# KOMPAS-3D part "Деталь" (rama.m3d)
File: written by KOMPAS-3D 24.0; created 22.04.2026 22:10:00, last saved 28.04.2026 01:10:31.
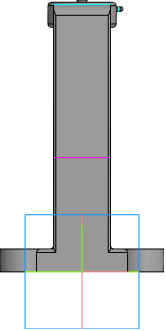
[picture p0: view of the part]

Document properties: Автор: mrdid; Полное имя файла: C:\Работа\ГОТОВЫЕ ИСХОДНИКИ\VSO2130M-F-S Клапан запорный сильфонный DN.ru Ду15-100 Ру40\исходные материалы\DN25\rama.m3d

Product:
- Part/product: Деталь
    Масса: 1.121141

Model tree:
1. Эскиз:2  (with: Ребро.Элемент выдавливания:14)
2. Элемент выдавливания:1
     Расстояние 1 = 10
3. Эскиз:3  (with: Грань.Элемент выдавливания:1, Ребро.Элемент выдавливания:1)
4. Элемент выдавливания:2
     Расстояние 2 = 10
5. Эскиз:4  (with: Грань.Элемент выдавливания:1)
6. Элемент выдавливания:3
     Расстояние 1 = 4.5
7. Эскиз:5  (with: Грань.Элемент выдавливания:3, Ребро.Элемент выдавливания:3)
8. Элемент выдавливания:4
     Расстояние 1 = 10
9. Эскиз:6  (with: Грань.Элемент выдавливания:1, Ребро.Элемент выдавливания:1)
10. Элемент выдавливания:5
     Расстояние 1 = 40
11. Эскиз:23  (with: Грань.Элемент выдавливания:4, Ребро.Элемент выдавливания:4)
12. Элемент выдавливания:21
     Расстояние 1 = 11
13. Эскиз:7  (with: Грань.Элемент выдавливания:21, Ребро.Элемент выдавливания:3)
14. Элемент выдавливания:6
     Расстояние 2 = 3
15. Эскиз:8  (with: Грань.Элемент выдавливания:5, Ребро.Элемент выдавливания:5)
16. Смещенная плоскость:1  (with: Грань.Элемент выдавливания:5)
17. Эскиз:9
18. Элемент по сечениям:1
19. Элемент по сечениям:2
20. Эскиз:10
21. Элемент выдавливания:8
     Расстояние 2 = 6
22. Эскиз:11  (with: Грань.Элемент выдавливания:8, Ребро.Элемент выдавливания:3)
23. Элемент выдавливания:9  (with: Грань.Элемент выдавливания:8)
     Расстояние 1 = 1; Расстояние 2 = 10; Смещение 2 = 4
24. Эскиз:12  (with: Грань.Элемент выдавливания:9, Ребро.Элемент выдавливания:9)
25. Элемент выдавливания:10
     Расстояние 1 = 5
26. Эскиз:13  (with: Грань.Элемент выдавливания:21, Ребро.Элемент выдавливания:3)
27. Элемент выдавливания:11  (with: Грань.Элемент выдавливания:10)
     Расстояние 1 = 66.488
28. Смещенная плоскость:2  (with: Грань.Элемент выдавливания:21)
29. Эскиз:14  (with: Ребро.Элемент по сечениям:2, Ребро.Элемент по сечениям:1)
30. Элемент выдавливания:12
     Расстояние 1 = 5
31. Эскиз:15  (with: Грань.Элемент выдавливания:12, Ребро.Элемент выдавливания:3)
32. Элемент выдавливания:13
     Расстояние 1 = 5
33. Эскиз:16  (with: Ребро.Элемент выдавливания:5, Ребро.Элемент выдавливания:1, Ребро.Элемент выдавливания:4)
34. Элемент выдавливания:14
     Расстояние 1 = 4
35. Элемент выдавливания:15
     Расстояние 1 = 2
36. Эскиз:17  (with: Ребро.Элемент выдавливания:5, Ребро.Элемент выдавливания:14)
37. Элемент выдавливания:16
     Расстояние 1 = 36
38. Скругление:1  (with: Ребро.Элемент выдавливания:1, Ребро.Элемент выдавливания:3)
     Радиус = 1.5
39. Скругление:2  (with: Ребро.Элемент выдавливания:9, Ребро.Элемент выдавливания:10, Ребро.Элемент выдавливания:13, Ребро.Элемент выдавливания:4)
40. Эскиз:18  (with: Грань.Элемент выдавливания:9)
41. Элемент выдавливания:17
     Расстояние 1 = 1
42. Скругление:3  (with: Ребро.Элемент по сечениям:2, Ребро.Элемент по сечениям:1)
     Радиус = 5
43. Скругление:4  (with: Ребро.Элемент выдавливания:8)
     Радиус = 0.5
44. Скругление:5  (with: Ребро.Элемент выдавливания:14)
     Радиус = 5
45. Эскиз:19  (with: Ребро.Элемент выдавливания:17)
46. Элемент выдавливания:18  (with: Грань.Элемент выдавливания:9)
     Смещение 1 = 5
47. Смещенная плоскость:3  (with: Грань.Элемент выдавливания:18)
     Расстояние = 2
48. Эскиз:20  (with: Ребро.Элемент выдавливания:18)
49. Элемент выдавливания:19
     Расстояние 2 = 0.2
50. Скругление:6  (with: Ребро.Элемент выдавливания:18)
     Радиус = 1
51. Эскиз:21  (with: Ребро.Элемент выдавливания:19)
52. Элемент выдавливания:20
     Расстояние 1 = 10
53. Скругление:7  (with: Ребро.Элемент по сечениям:2, Ребро.Элемент выдавливания:5, Ребро.Элемент по сечениям:1)
     Радиус = 1
54. Фаска:1  (with: Ребро.Элемент по сечениям:1, Ребро.Элемент по сечениям:2)
     Угол = 45; Длина 1 = 2; Длина 2 = 2
55. Массив по концентрической сетке:1  (with: Элемент выдавливания:2, Эскиз:3)  (labels: Клапан запорный DN.ru Ду25 Ру40)  (4 pattern instances)
     Шаг 2 = 360

Expressions: v249/2; DN/2
Referenced files in C:\Работа\ГОТОВЫЕ ИСХОДНИКИ\VSO2130M-F-S Клапан запорный сильфонный DN.ru Ду15-100 Ру40\исходные материалы\DN25\: VSO2130M-F-S Клапан запорный DN.ru Ду25 Ру40.a3d
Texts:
  DN+5
  Ось Y.Начало координат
